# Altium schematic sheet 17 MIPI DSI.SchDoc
size 297 x 209 mm
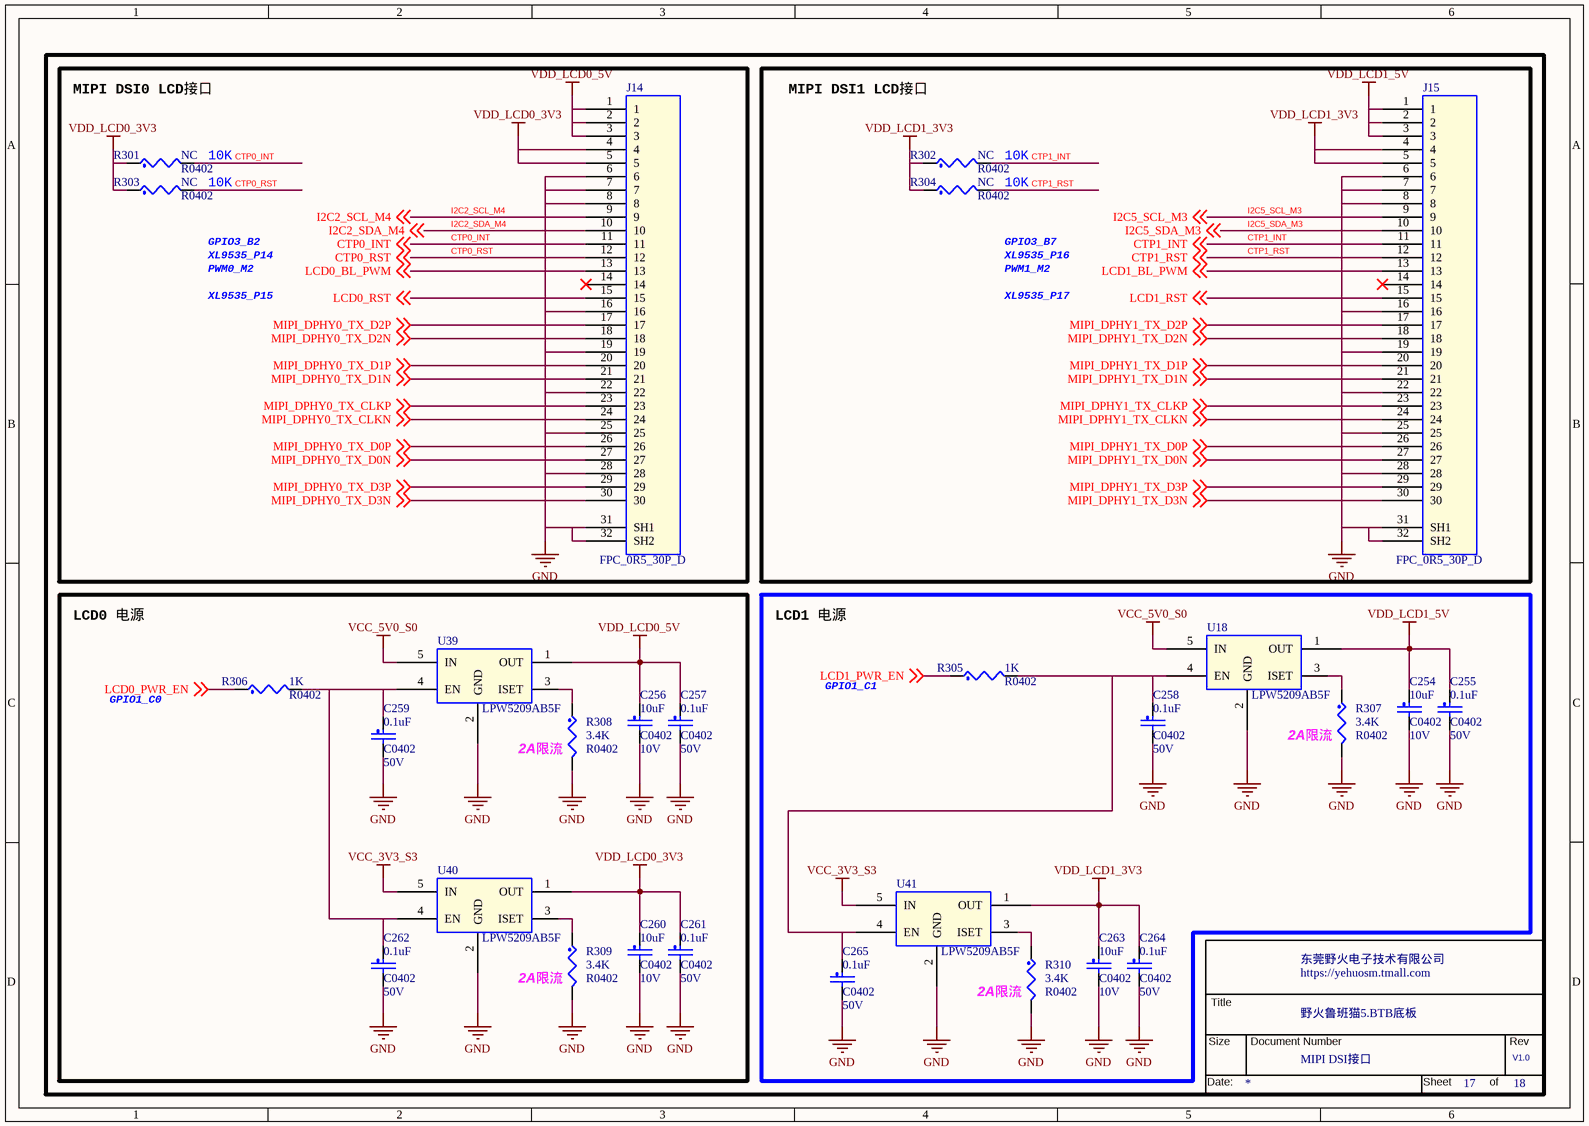
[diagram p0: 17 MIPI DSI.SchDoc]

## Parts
*  Doc: MIPI DSI接口  RevCode: V1.0  Title: 野火鲁班猫5.BTB底板  OrgName: 东莞野火电子技术有限公司  Page Number: 17  Page Count: 18  (hidden comment: TitleBlock_YHSCH)  (graphical)
C254  10uF  Voltage: 10V  [C0402]
C255  0.1uF  Voltage: 50V  [C0402]
C256  10uF  Voltage: 10V  [C0402]
C257  0.1uF  Voltage: 50V  [C0402]
C258  0.1uF  Voltage: 50V  [C0402]
C259  0.1uF  Voltage: 50V  [C0402]
C260  10uF  Voltage: 10V  [C0402]
C261  0.1uF  Voltage: 50V  [C0402]
C262  0.1uF  Voltage: 50V  [C0402]
C263  10uF  Voltage: 10V  [C0402]
C264  0.1uF  Voltage: 50V  [C0402]
C265  0.1uF  Voltage: 50V  [C0402]
J14  FPC_0R5_30P_D  [FPC-30P-0P5]
J15  FPC_0R5_30P_D  [FPC-30P-0P5]
R301  NC  [R0402]
R302  NC  [R0402]
R303  NC  [R0402]
R304  NC  [R0402]
R305  1K  [R0402]
R306  1K  [R0402]
R307  3.4K  [R0402]
R308  3.4K  [R0402]
R309  3.4K  [R0402]
R310  3.4K  [R0402]
U18  LPW5209AB5F  [SOT23-5]
U39  LPW5209AB5F  [SOT23-5]
U40  LPW5209AB5F  [SOT23-5]
U41  LPW5209AB5F  [SOT23-5]

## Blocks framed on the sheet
MIPI DSI0 LCD接口: J14 R301 R303
MIPI DSI1 LCD接口: J15 R302 R304
LCD0 电源: C256 C257 C259-C262 R306 R308 R309 U39 U40
LCD1 电源: C254 C255 C258 C263-C265 R305 R307 R310 U18 U41

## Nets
GND: C254.2 C255.2 C256.2 C257.2 C258.2 C259.2 C260.2 C261.2 C262.2 C263.2 C264.2 C265.2 J14.6 J14.7 J14.8 J14.16 J14.19 J14.22 J14.25 J14.28 J14.31(SH1) J14.32(SH2) J15.6 J15.7 J15.8 J15.16 J15.19 J15.22 J15.25 J15.28 J15.31(SH1) J15.32(SH2) R307.2 R308.2 R309.2 R310.2 U18.2(GND) U39.2(GND) U40.2(GND) U41.2(GND)
VCC_3V3_S3: U40.5(IN) U41.5(IN)
VCC_5V0_S0: U18.5(IN) U39.5(IN)
VDD_LCD0_3V3: C260.1 C261.1 J14.4 J14.5 R301.1 R303.1 U40.1(OUT)
VDD_LCD0_5V: C256.1 C257.1 J14.1 J14.2 J14.3 U39.1(OUT)
VDD_LCD1_3V3: C263.1 C264.1 J15.4 J15.5 R302.1 R304.1 U41.1(OUT)
VDD_LCD1_5V: C254.1 C255.1 J15.1 J15.2 J15.3 U18.1(OUT)
CTP0_INT: J14.11 R301.2 ; off-sheet CTP0_INT
CTP0_RST: J14.12 R303.2 ; off-sheet CTP0_RST
CTP1_INT: J15.11 R302.2 ; off-sheet CTP1_INT
CTP1_RST: J15.12 R304.2 ; off-sheet CTP1_RST
I2C2_SCL_M4: J14.9 ; off-sheet I2C2_SCL_M4
I2C2_SDA_M4: J14.10 ; off-sheet I2C2_SDA_M4
I2C5_SCL_M3: J15.9 ; off-sheet I2C5_SCL_M3
I2C5_SDA_M3: J15.10 ; off-sheet I2C5_SDA_M3
LCD0_BL_PWM: J14.13 ; off-sheet LCD0_BL_PWM
LCD0_PWR_EN: R306.1 ; off-sheet LCD0_PWR_EN
LCD0_RST: J14.15 ; off-sheet LCD0_RST
LCD1_BL_PWM: J15.13 ; off-sheet LCD1_BL_PWM
LCD1_PWR_EN: R305.1 ; off-sheet LCD1_PWR_EN
LCD1_RST: J15.15 ; off-sheet LCD1_RST
MIPI_DPHY0_TX_CLKN: J14.24 ; off-sheet MIPI_DPHY0_TX_CLKN
MIPI_DPHY0_TX_CLKP: J14.23 ; off-sheet MIPI_DPHY0_TX_CLKP
MIPI_DPHY0_TX_D0N: J14.27 ; off-sheet MIPI_DPHY0_TX_D0N
MIPI_DPHY0_TX_D0P: J14.26 ; off-sheet MIPI_DPHY0_TX_D0P
MIPI_DPHY0_TX_D1N: J14.21 ; off-sheet MIPI_DPHY0_TX_D1N
MIPI_DPHY0_TX_D1P: J14.20 ; off-sheet MIPI_DPHY0_TX_D1P
MIPI_DPHY0_TX_D2N: J14.18 ; off-sheet MIPI_DPHY0_TX_D2N
MIPI_DPHY0_TX_D2P: J14.17 ; off-sheet MIPI_DPHY0_TX_D2P
MIPI_DPHY0_TX_D3N: J14.30 ; off-sheet MIPI_DPHY0_TX_D3N
MIPI_DPHY0_TX_D3P: J14.29 ; off-sheet MIPI_DPHY0_TX_D3P
MIPI_DPHY1_TX_CLKN: J15.24 ; off-sheet MIPI_DPHY1_TX_CLKN
MIPI_DPHY1_TX_CLKP: J15.23 ; off-sheet MIPI_DPHY1_TX_CLKP
MIPI_DPHY1_TX_D0N: J15.27 ; off-sheet MIPI_DPHY1_TX_D0N
MIPI_DPHY1_TX_D0P: J15.26 ; off-sheet MIPI_DPHY1_TX_D0P
MIPI_DPHY1_TX_D1N: J15.21 ; off-sheet MIPI_DPHY1_TX_D1N
MIPI_DPHY1_TX_D1P: J15.20 ; off-sheet MIPI_DPHY1_TX_D1P
MIPI_DPHY1_TX_D2N: J15.18 ; off-sheet MIPI_DPHY1_TX_D2N
MIPI_DPHY1_TX_D2P: J15.17 ; off-sheet MIPI_DPHY1_TX_D2P
MIPI_DPHY1_TX_D3N: J15.30 ; off-sheet MIPI_DPHY1_TX_D3N
MIPI_DPHY1_TX_D3P: J15.29 ; off-sheet MIPI_DPHY1_TX_D3P
NetC258_1: C258.1 C265.1 R305.2 U18.4(EN) U41.4(EN)
NetC259_1: C259.1 C262.1 R306.2 U39.4(EN) U40.4(EN)
NetR307_1: R307.1 U18.3(ISET)
NetR308_1: R308.1 U39.3(ISET)
NetR309_1: R309.1 U40.3(ISET)
NetR310_1: R310.1 U41.3(ISET)

Not connected (* = marked no-connect by the designer): J14 14*; J15 14*

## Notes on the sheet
- 10K
- GPIO3_B2
- PWM0_M2
- XL9535_P14
- GPIO3_B7
- PWM1_M2
- XL9535_P16
- XL9535_P15
- XL9535_P17
- GPIO1_C0
- GPIO1_C1
- 2A限流

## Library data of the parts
* = TitleBlock_YHSCH: Cage Code: 1
C254 C256 C263 = CAP_NP: CLASS: DISCRETE; 生命周期: 量产; 价格: 0.518415; 规格书: 三星电容.pdf; 类别: 贴片电容0402; 品牌: 三星; 条码: EBF29060247; 规格编号: CL05A106MP8NUB8; 规格: 贴片电容10uF 20% 10V X5R 0402
C255 C257-C259 C264 C265 = CAP_NP: CLASS: DISCRETE; 规格: 贴片电容0.1uF 10% 50V X5R 0402; 规格编号: 0402X104K500NT; 条码: EBF29060118; 品牌: 风华; 类别: 贴片电容0402; 规格书: 风华电容.pdf; 价格: 0.029826; 生命周期: 量产
C260 = CAP_NP: CLASS: DISCRETE; 规格: 贴片电容10uF 20% 10V X5R 0402; 规格编号: CL05A106MP8NUB8; 条码: EBF29060247; 品牌: 三星; 类别: 贴片电容0402; 规格书: 三星电容.pdf; 价格: 0.518415; 生命周期: 量产
C261 C262 = CAP_NP: CLASS: DISCRETE; 生命周期: 量产; 价格: 0.029826; 规格书: 风华电容.pdf; 类别: 贴片电容0402; 品牌: 风华; 条码: EBF29060118; 规格编号: 0402X104K500NT; 规格: 贴片电容0.1uF 10% 50V X5R 0402
J14 J15 = FPC-30P: 规格: FPC连接器 针脚数30 间距0.5mm 高度2.0mm 下接 卧贴 翻盖式; 规格编号: FPC-05F-30PH20; 条码: EBF29040079; 品牌: 讯普; 类别: FPC连接器; 规格书: FPC-05F-NPH20.pdf; 生命周期: 量产
R301-R304 = RES: CLASS: DISCRETE; 类别: 贴片电阻0402; 条码: EBF29070087; 规格: 贴片电阻NC 预留
R305 R306 = RES: CLASS: DISCRETE; 规格: 贴片电阻1K 1% 1/16W 0402; 规格编号: RI0402L1001FT; 条码: EBF29070050; 品牌: 合科泰; 类别: 贴片电阻0402; 规格书: 合科泰-RI系列电阻.pdf; 生命周期: 量产
R307 R308 R310 = RES: CLASS: DISCRETE; 规格: 贴片电阻3.4K 1% 1/16W 0402; 规格编号: RI0402L3401FT; 条码: EBF29070186; 品牌: 合科泰; 类别: 贴片电阻0402; 规格书: 合科泰-RI系列电阻.pdf; 生命周期: 量产
R309 = RES: CLASS: DISCRETE; 生命周期: 量产; 规格书: 合科泰-RI系列电阻.pdf; 类别: 贴片电阻0402; 品牌: 合科泰; 条码: EBF29070186; 规格编号: RI0402L3401FT; 规格: 贴片电阻3.4K 1% 1/16W 0402
U18 U39 U40 = LPW5209AB5F: 生命周期: 量产; 价格: 0.468063; 规格书: 微源半导体_LPW5209AB5F.pdf; 类别: 功率开关; 品牌: 微源半导体; 条码: EBF29280015; 规格: 集成电源开关 导通电阻：80mΩ 最大可设置保护电流：2.1A 输入电压：2.5V~6V 静态电流：30uA 其他功能：软启动、短路保护、热保护
U41 = LPW5209AB5F: 规格: 集成电源开关 导通电阻：80mΩ 最大可设置保护电流：2.1A 输入电压：2.5V~6V 静态电流：30uA 其他功能：软启动、短路保护、热保护; 条码: EBF29280015; 品牌: 微源半导体; 类别: 功率开关; 规格书: 微源半导体_LPW5209AB5F.pdf; 价格: 0.468063; 生命周期: 量产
